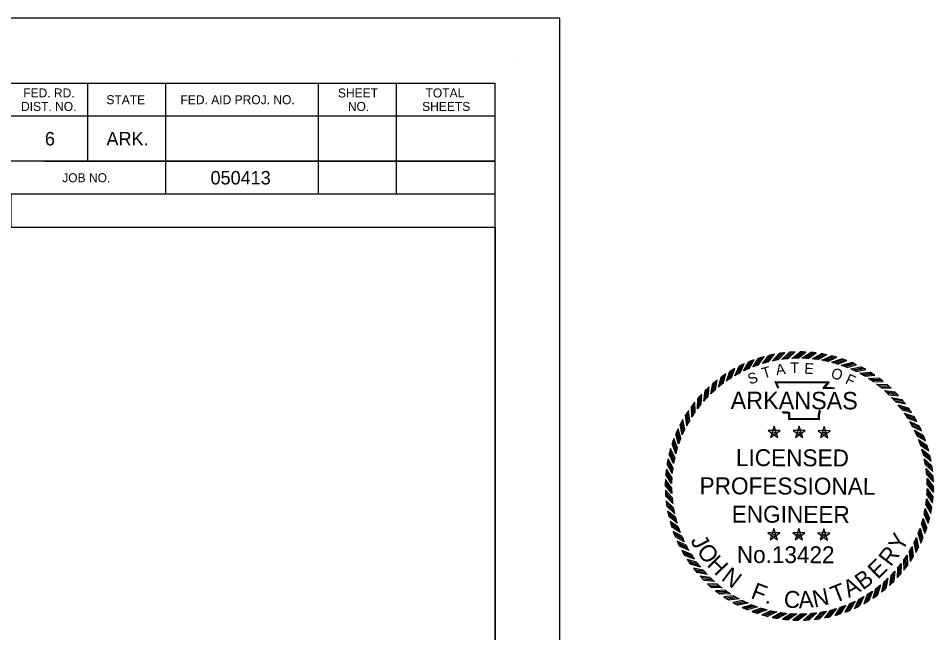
# Model space of a CAD drawing. Extents: x 759422 to 1467355, y 1662254 to 1691786.
# Drawn here: x 1466947.3 to 1467354.5, y 1691513 to 1691786.2 of the extents above; entities that cross this region are included whole.
import ezdxf

# ---------------------------------------------------------------- set-up
doc = ezdxf.new("R2010")
doc.units = 0
doc.layers.add('1', color=7, linetype='Continuous')
doc.layers.add('Default', color=7, linetype='Continuous')

# ---------------------------------------------------------------- blocks, each defined once
blk = doc.blocks.new('STAR')
at = {"layer": 'Default'}
for p, q in [((0.0587, 0.0188), (-0.059, 0.0189)), ((-0.0589, 0.0188), (0.0363, -0.0505)), ((-0.0001, 0.0615), (-0.0366, -0.0504)), ((-0.0365, -0.0503), (0.0589, 0.0188)), ((-0.0085, 0), (0.009, 0)), ((0.0362, -0.0503), (0, 0.0617)), ((0, 0.0063), (0, -0.0085))]:
    blk.add_line(p, q, dxfattribs=at)
blk = doc.blocks.new('RP')
at = {"layer": 'Default'}
for p, q in [((-0.0781, 1.2656), (0.003, 1.33)), ((-0.058, 1.2667), (0.0216, 1.3299)), ((-0.0375, 1.2674), (0.0405, 1.3294)), ((-0.0176, 1.2679), (0.059, 1.3287))]:
    blk.add_line(p, q, dxfattribs=at)
for radius, start, end in [(1.33, 87.45624, 89.86992), (1.268, 90.79335, 93.53072)]:
    blk.add_arc((0, 0), radius, start, end, dxfattribs=at)

msp = doc.modelspace()

# ---------------------------------------------------------------- linework, layer by layer
at = {"layer": '1'}
for p, q in [((1467170.36, 1691768.89), (1467170.36, 1691768.89)), ((1465564.06, 1691757.36), (1467159.42, 1691757.36)), ((1466978.12, 1691757.36), (1466978.12, 1691722.66)), ((1467012.82, 1691757.36), (1467012.82, 1691707.96)), ((1467080.72, 1691757.36), (1467080.72, 1691707.96)), ((1467115.42, 1691757.36), (1467115.42, 1691707.96)), ((1467159.42, 1690715.04), (1467159.42, 1691757.36)), ((1467159.42, 1691742.66), (1466943.92, 1691742.66)), ((1467159.42, 1691742.76), (1467159.42, 1691742.76)), ((1467159.42, 1691722.66), (1466943.92, 1691722.66)), ((1466958.72, 1691722.66), (1467159.42, 1691722.66)), ((1467159.42, 1691707.96), (1466748.12, 1691707.96)), ((1466943.92, 1691693.36), (1467159.42, 1691693.36))]:
    msp.add_line(p, q, dxfattribs=at)
for points in [[(1467188.26, 1691786.2), (1465488.26, 1691786.2), (1465488.26, 1690686.2), (1467188.26, 1690686.2)], [(1465564.06, 1691229.74), (1465564.06, 1691757.36), (1466748.12, 1691757.36), (1466748.12, 1691707.96), (1466943.92, 1691707.96), (1466943.92, 1691693.36), (1467159.42, 1691693.36), (1467159.42, 1691229.74)], [(1465564.06, 1691757.36), (1466748.12, 1691757.36), (1466748.12, 1691707.96), (1466943.92, 1691707.96), (1466943.92, 1691693.36), (1467159.42, 1691693.36), (1467159.42, 1691229.74), (1465564.06, 1691229.74)]]:
    msp.add_lwpolyline(points, close=True, dxfattribs=at)
at = {"layer": 'Default'}
for points in [[(1467285.35, 1691621.64), (1467283.97, 1691624.67), (1467308.09, 1691624.6), (1467306.07, 1691622.07), (1467307.71, 1691622.09), (1467309.08, 1691622.1), (1467310.44, 1691621.95)], [(1467285.7, 1691621.8), (1467284.56, 1691624.28), (1467307.3, 1691624.22), (1467305.26, 1691621.68), (1467307.71, 1691621.71), (1467309.06, 1691621.72), (1467310.4, 1691621.57)], [(1467304.24, 1691611.47), (1467303.83, 1691611.13), (1467303.69, 1691610.63), (1467303.55, 1691609.38), (1467303.55, 1691607.72), (1467290.08, 1691607.76), (1467290.09, 1691610.01), (1467290.09, 1691610.51), (1467289.54, 1691610.68), (1467287.63, 1691610.69), (1467287.29, 1691611.21)], [(1467304, 1691611.76), (1467303.5, 1691611.35), (1467303.32, 1691610.71), (1467303.17, 1691609.41), (1467303.17, 1691608.1), (1467290.46, 1691608.14), (1467290.47, 1691610.01), (1467290.47, 1691610.79), (1467289.6, 1691611.06), (1467287.84, 1691611.07), (1467287.61, 1691611.42)]]:
    msp.add_lwpolyline(points, dxfattribs=at)

# ---------------------------------------------------------------- block references
for name, p, xscale, yscale, rotation in [('RP', (1467294.78, 1691578.2), 44.855502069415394, 44.85550206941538, 17.80419999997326), ('RP', (1467294.78, 1691578.2), 44.855502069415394, 44.85550206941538, 13.304199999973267), ('RP', (1467294.78, 1691578.2), 44.855502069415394, 44.855502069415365, 8.804199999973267), ('RP', (1467294.78, 1691578.2), 44.85550206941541, 44.85550206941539, 4.304199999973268), ('RP', (1467294.78, 1691578.2), 44.8555020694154, 44.85550206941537, -0.19580000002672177), ('RP', (1467294.78, 1691578.2), 44.8555020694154, 44.85550206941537, -4.695800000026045), ('RP', (1467294.78, 1691578.2), 44.85550206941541, 44.85550206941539, -9.195800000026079), ('RP', (1467294.78, 1691578.2), 44.855502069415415, 44.85550206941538, -13.695800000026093), ('RP', (1467294.78, 1691578.2), 44.85550206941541, 44.85550206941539, -18.195800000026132), ('RP', (1467294.78, 1691578.2), 44.855502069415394, 44.855502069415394, 26.804199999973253), ('RP', (1467294.78, 1691578.2), 44.85550206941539, 44.85550206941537, 22.30419999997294), ('RP', (1467294.78, 1691578.2), 44.8555020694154, 44.85550206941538, -22.69580000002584), ('RP', (1467294.78, 1691578.2), 44.855502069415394, 44.85550206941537, -27.19580000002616), ('RP', (1467294.78, 1691578.2), 44.85550206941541, 44.8555020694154, -31.695800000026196), ('RP', (1467294.78, 1691578.2), 44.85550206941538, 44.85550206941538, 35.80419999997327), ('RP', (1467294.78, 1691578.2), 44.85550206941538, 44.85550206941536, 31.30419999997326), ('RP', (1467294.78, 1691578.2), 44.8555020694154, 44.855502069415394, -36.195800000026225), ('RP', (1467294.78, 1691578.2), 44.85550206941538, 44.85550206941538, 40.304199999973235), ('RP', (1467294.78, 1691578.2), 44.85550206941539, 44.8555020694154, -40.69580000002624), ('RP', (1467294.78, 1691578.2), 44.85550206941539, 44.85550206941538, -45.195800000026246), ('RP', (1467294.78, 1691578.2), 44.8555020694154, 44.8555020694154, 49.304199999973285), ('RP', (1467294.78, 1691578.2), 44.85550206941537, 44.855502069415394, 44.80419999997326), ('RP', (1467294.78, 1691578.2), 44.85550206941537, 44.85550206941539, -49.695800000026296), ('RP', (1467294.78, 1691578.2), 44.8555020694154, 44.85550206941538, 53.804199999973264), ('RP', (1467294.78, 1691578.2), 44.85550206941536, 44.855502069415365, -54.1958000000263), ('RP', (1467294.78, 1691578.2), 44.85550206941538, 44.85550206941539, 58.304199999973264), ('RP', (1467294.78, 1691578.2), 44.85550206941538, 44.85550206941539, -58.695800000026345), ('RP', (1467294.78, 1691578.2), 44.85550206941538, 44.855502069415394, 62.804199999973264), ('RP', (1467294.78, 1691578.2), 44.85550206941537, 44.85550206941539, -63.19580000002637), ('RP', (1467294.78, 1691578.2), 44.85550206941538, 44.8555020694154, 67.30419999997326), ('STAR', (1467283.6, 1691602.05), 44.8555020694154, 44.85550206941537, -0.19580000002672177), ('STAR', (1467294.7, 1691602.02), 44.8555020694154, 44.85550206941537, -0.19580000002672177), ('STAR', (1467305.79, 1691601.98), 44.8555020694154, 44.85550206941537, -0.19580000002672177), ('RP', (1467294.78, 1691578.2), 44.85550206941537, 44.85550206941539, -67.6958000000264), ('RP', (1467294.78, 1691578.2), 44.85550206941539, 44.855502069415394, 71.80419999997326), ('RP', (1467294.78, 1691578.2), 44.85550206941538, 44.8555020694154, -72.19580000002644), ('RP', (1467294.78, 1691578.2), 44.85550206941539, 44.85550206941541, 76.30419999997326), ('RP', (1467294.78, 1691578.2), 44.85550206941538, 44.85550206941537, -76.69580000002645), ('RP', (1467294.78, 1691578.2), 44.85550206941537, 44.8555020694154, 80.80419999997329), ('RP', (1467294.78, 1691578.2), 44.85550206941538, 44.8555020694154, -81.19580000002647), ('RP', (1467294.78, 1691578.2), 44.85550206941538, 44.855502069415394, -85.69580000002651), ('RP', (1467294.78, 1691578.2), 44.855502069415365, 44.85550206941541, 85.30419999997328), ('RP', (1467294.78, 1691578.2), 44.85550206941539, 44.85550206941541, 89.80419999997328), ('RP', (1467294.78, 1691578.2), 44.85550206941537, 44.8555020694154, -90.19580000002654), ('RP', (1467294.78, 1691578.2), 44.85550206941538, 44.85550206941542, 94.30419999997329), ('RP', (1467294.78, 1691578.2), 44.85550206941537, 44.85550206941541, -94.69580000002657), ('RP', (1467294.78, 1691578.2), 44.85550206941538, 44.855502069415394, 98.8041999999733), ('RP', (1467294.78, 1691578.2), 44.85550206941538, 44.855502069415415, -99.19580000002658), ('RP', (1467294.78, 1691578.2), 44.85550206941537, 44.8555020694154, 103.30419999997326), ('RP', (1467294.78, 1691578.2), 44.85550206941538, 44.8555020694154, -103.69580000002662), ('RP', (1467294.78, 1691578.2), 44.85550206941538, 44.855502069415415, 107.80419999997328), ('RP', (1467294.78, 1691578.2), 44.85550206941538, 44.85550206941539, -108.19580000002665), ('RP', (1467294.78, 1691578.2), 44.85550206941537, 44.85550206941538, 112.3041999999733), ('STAR', (1467283.45, 1691556.56), 44.8555020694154, 44.85550206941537, -0.19580000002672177), ('STAR', (1467294.54, 1691556.52), 44.8555020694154, 44.85550206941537, -0.19580000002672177), ('STAR', (1467305.64, 1691556.48), 44.8555020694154, 44.85550206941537, -0.19580000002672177), ('RP', (1467294.78, 1691578.2), 44.85550206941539, 44.855502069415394, -112.69580000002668), ('RP', (1467294.78, 1691578.2), 44.85550206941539, 44.8555020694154, 116.80419999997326), ('RP', (1467294.78, 1691578.2), 44.85550206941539, 44.85550206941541, -117.19580000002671), ('RP', (1467294.78, 1691578.2), 44.855502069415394, 44.85550206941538, 121.30419999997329), ('RP', (1467294.78, 1691578.2), 44.85550206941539, 44.8555020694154, -121.69580000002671), ('RP', (1467294.78, 1691578.2), 44.85550206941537, 44.85550206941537, 125.80419999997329), ('RP', (1467294.78, 1691578.2), 44.8555020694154, 44.8555020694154, -126.19580000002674), ('RP', (1467294.78, 1691578.2), 44.85550206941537, 44.85550206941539, 130.3041999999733), ('RP', (1467294.78, 1691578.2), 44.85550206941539, 44.85550206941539, -130.6958000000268), ('RP', (1467294.78, 1691578.2), 44.855502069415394, 44.85550206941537, 134.80419999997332), ('RP', (1467294.78, 1691578.2), 44.85550206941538, 44.85550206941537, -139.69580000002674), ('RP', (1467294.78, 1691578.2), 44.85550206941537, 44.855502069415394, -135.19580000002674), ('RP', (1467294.78, 1691578.2), 44.85550206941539, 44.85550206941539, 139.30419999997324), ('RP', (1467294.78, 1691578.2), 44.85550206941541, 44.855502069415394, 143.8041999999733), ('RP', (1467294.78, 1691578.2), 44.85550206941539, 44.855502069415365, -144.19580000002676), ('RP', (1467294.78, 1691578.2), 44.85550206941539, 44.85550206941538, 148.3041999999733), ('RP', (1467294.78, 1691578.2), 44.8555020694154, 44.855502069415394, 152.8041999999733), ('RP', (1467294.78, 1691578.2), 44.85550206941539, 44.85550206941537, -153.1958000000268), ('RP', (1467294.78, 1691578.2), 44.85550206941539, 44.85550206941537, -148.69580000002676), ('RP', (1467294.78, 1691578.2), 44.8555020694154, 44.85550206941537, 157.3041999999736), ('RP', (1467294.78, 1691578.2), 44.85550206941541, 44.85550206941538, 161.80419999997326), ('RP', (1467294.78, 1691578.2), 44.855502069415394, 44.85550206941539, -162.19580000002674), ('RP', (1467294.78, 1691578.2), 44.8555020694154, 44.85550206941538, -157.6958000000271), ('RP', (1467294.78, 1691578.2), 44.855502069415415, 44.85550206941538, 166.3041999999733), ('RP', (1467294.78, 1691578.2), 44.8555020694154, 44.855502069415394, 170.8041999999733), ('RP', (1467294.78, 1691578.2), 44.8555020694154, 44.85550206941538, 175.3041999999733), ('RP', (1467294.78, 1691578.2), 44.85550206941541, 44.85550206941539, 179.8041999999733), ('RP', (1467294.78, 1691578.2), 44.8555020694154, 44.85550206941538, -175.69580000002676), ('RP', (1467294.78, 1691578.2), 44.85550206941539, 44.85550206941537, -171.19580000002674), ('RP', (1467294.78, 1691578.2), 44.855502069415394, 44.85550206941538, -166.69580000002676)]:
    msp.add_blockref(name, p, dxfattribs=dict(at, xscale=xscale, yscale=yscale, rotation=rotation))

# ---------------------------------------------------------------- texts
at = {"layer": '1'}
for s, height, p in [('FED. RD.', 4, (1466949.49, 1691751.01)), ('SHEET', 4, (1467089.49, 1691751.01)), ('TOTAL', 4, (1467128.47, 1691751.01)), ('DIST. NO.', 4, (1466948.52, 1691745.01)), ('STATE', 4, (1466986.49, 1691748.01)), ('FED. AID PROJ. NO.', 4, (1467019.46, 1691748.01)), ('NO.', 4, (1467093.91, 1691745.01)), ('SHEETS', 4, (1467126.96, 1691745.01)), ('6', 6, (1466959.15, 1691729.66)), ('ARK.', 6, (1466986.54, 1691729.66)), ('JOB NO.', 4, (1466966.84, 1691713.31)), ('050413', 6, (1467032.83, 1691712.31))]:
    msp.add_text(s, height=height, dxfattribs=at).set_placement(p)
at = {"layer": 'Default'}
for s, height, rotation, p in [('T', 4.76, 16.7057, (1467278.85, 1691625.96)), ('A', 4.76, 8.483, (1467284.63, 1691627.45)), ('T', 4.76, 1.2831, (1467290.78, 1691628.38)), ('E', 4.76, 356.4762, (1467296.87, 1691628.21)), ('O', 4.76, 341.026, (1467308.42, 1691626.54)), ('S', 4.76, 19.5768, (1467272.79, 1691623.27)), ('F', 4.76, 335.167, (1467314.83, 1691624.01)), ('ARKANSAS', 7.767, 359.8042, (1467264.2, 1691612.47)), ('LICENSED', 7.52, 359.8042, (1467266.53, 1691587.11)), ('PROFESSIONAL', 7.5196, 359.8042, (1467250.37, 1691574.59)), ('ENGINEER', 7.52, 359.8042, (1467264.65, 1691561.96)), ('Y', 7.52, 62.5392, (1467340.62, 1691548.69)), ('J', 7.52, 297.2813, (1467246.18, 1691554.03)), ('O', 7.52, 304.1899, (1467248.84, 1691549.42)), ('No.13422', 7.49, 359.8042, (1467266.96, 1691544.03)), ('R', 7.52, 52.7437, (1467335.37, 1691542.06)), ('H', 7.52, 314.7447, (1467253.28, 1691542.94)), ('E', 7.52, 44.306, (1467329.65, 1691536.47)), ('N', 7.52, 322.9417, (1467259.63, 1691536.65)), ('B', 7.52, 36.505, (1467323.01, 1691531.68)), ('F', 7.52, 339.0288, (1467272.75, 1691528.51)), ('N', 7.52, 12.0703, (1467301.44, 1691524.17)), ('T', 7.52, 21.4329, (1467310.51, 1691526.05)), ('A', 7.52, 28.8562, (1467316.76, 1691528.4)), ('C', 7.52, 356.1028, (1467287.67, 1691524.29)), ('A', 7.52, 3.9092, (1467294.57, 1691523.79)), ('.', 7.52, 344.7037, (1467279.17, 1691526.28))]:
    msp.add_text(s, height=height, rotation=rotation, dxfattribs=at).set_placement(p)

doc.saveas('drawing.dxf')
